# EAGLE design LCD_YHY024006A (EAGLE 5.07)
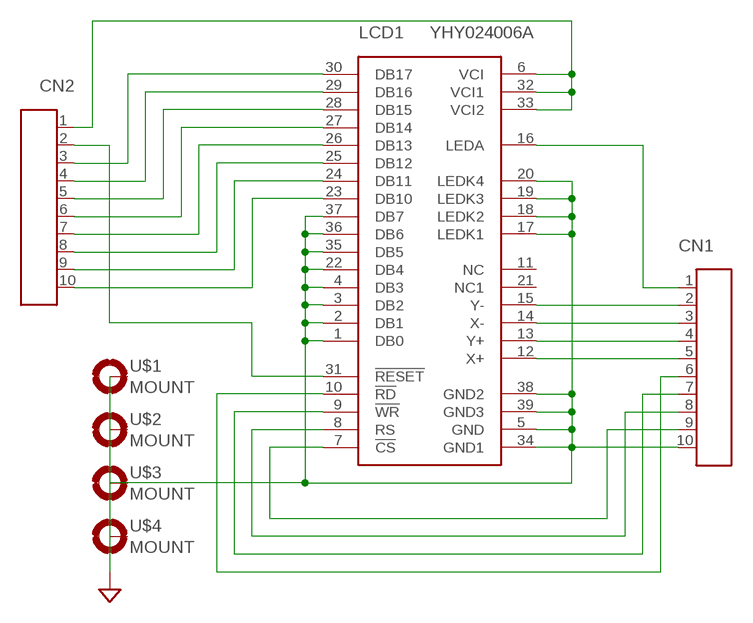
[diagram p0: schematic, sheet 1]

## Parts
CN1  CON_10P  [CON_HRS_DIP_10]
CN2  CON_10P  [CON_HRS_DIP_10]
LCD1  YHY024006A  LCD_YHY024006A  [LCD_YHY024006A]
U$1  MOUNT  MOUNT-PAD2.1  [PAD-2.1]
U$2  MOUNT  MOUNT-PAD2.1  [PAD-2.1]
U$3  MOUNT  MOUNT-PAD2.1  [PAD-2.1]
U$4  MOUNT  MOUNT-PAD2.1  [PAD-2.1]

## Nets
GND: CN1.10 LCD1.1(DB0) LCD1.2(DB1) LCD1.3(DB2) LCD1.4(DB3) LCD1.5(GND) LCD1.17(LEDK1) LCD1.18(LEDK2) LCD1.19(LEDK3) LCD1.20(LEDK4) LCD1.22(DB4) LCD1.34(GND1) LCD1.35(DB5) LCD1.36(DB6) LCD1.37(DB7) LCD1.38(GND2) LCD1.39(GND3) U$1.B2,1(MOUNT) U$2.B2,1(MOUNT) U$3.B2,1(MOUNT) U$4.B2,1(MOUNT)
N$1: CN2.3 LCD1.30(DB17)
N$2: CN2.4 LCD1.29(DB16)
N$3: CN2.5 LCD1.28(DB15)
N$4: CN2.6 LCD1.27(DB14)
N$5: CN2.7 LCD1.26(DB13)
N$6: CN2.8 LCD1.25(DB12)
N$7: CN2.9 LCD1.24(DB11)
N$8: CN2.10 LCD1.23(DB10)
N$9: CN2.2 LCD1.31(!RESET)
N$10: CN1.6 LCD1.10(!RD)
N$11: CN1.7 LCD1.9(!WR)
N$12: CN1.8 LCD1.8(RS)
N$13: CN1.9 LCD1.7(!CS)
N$14: CN1.2 LCD1.15(Y-)
N$15: CN1.3 LCD1.14(X-)
N$16: CN1.4 LCD1.13(Y+)
N$17: CN1.5 LCD1.12(X+)
N$19: CN2.1 LCD1.6(VCI) LCD1.32(VCI1) LCD1.33(VCI2)
N$20: CN1.1 LCD1.16(LEDA)
Unconnected: LCD1.11(NC) LCD1.21(NC1)

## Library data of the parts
CN1 CN2 = MyLib:CON_10P: 10P Molex Connector
LCD1 = MyLib:LCD_YHY024006A: 2.4" TFT Color LCD with Touch Screen
U$1-U$4 = MyLib:MOUNT-PAD: 2.1mm Mount Pad (Connectable to GND)

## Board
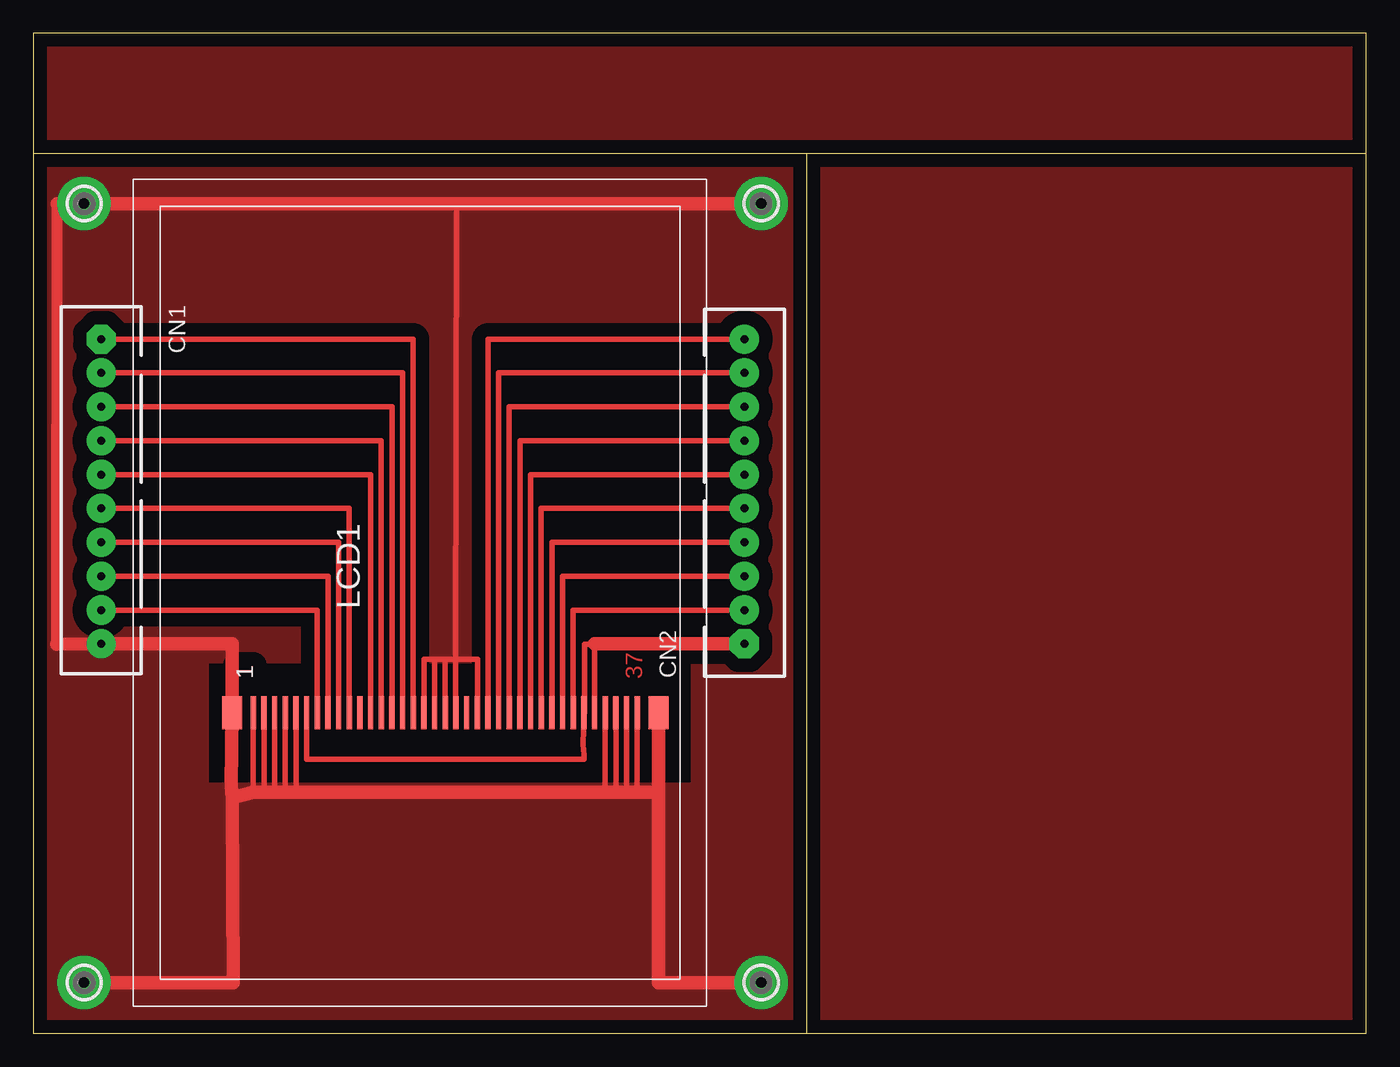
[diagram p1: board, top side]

Size 100 x 75 mm. Coordinates in mm from the lower left corner, seen from the top.
Outline: 58,0 0,0 0,66
Outline: 58,0 100,0 100,66
Outline: 100,66 100,75 0,75 0,66
Outline: 0,66 58,66
Outline: 58,66 100,66
Outline: 58,66 58,0
Copper layers (1*16): Top 0.035mm / dielectric 1.5mm / Bottom 0.035mm
Design rules "default": minimum track width 10mil, minimum drill 24mil, track to track 8mil, track to pad 8mil, pad to pad 8mil, via to via 8mil, smd to smd 8mil, copper to edge 40mil, drill to drill 8mil, minimum pad ring 10mil, minimum via ring 8mil, stop-mask expansion 4mil, vias tented up to drill 0mil, thermal gap 10mil

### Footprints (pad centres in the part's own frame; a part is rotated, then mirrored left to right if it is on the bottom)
CON_HRS_DIP_10 = drill 0.6 pad 2.184 octagon: 1 -11.43,0 | drill 0.6 pad 2.184 round: 2 -8.89,0; 3 -6.35,0; 4 -3.81,0; 5 -1.27,0; 6 1.27,0; 7 3.81,0; 8 6.35,0; 9 8.89,0; 10 11.43,0
LCD_YHY024006A = smd 2.5 x 0.4: 1 5,0; 2 5,-0.8; 3 5,-1.6; 4 5,-2.4; 5 5,-3.2; 6 5,-4; 7 5,-4.8; 8 5,-5.6; 9 5,-6.4; 10 5,-7.2; 11 5,-8; 12 5,-8.8; 13 5,-9.6; 14 5,-10.4; 15 5,-11.2; 16 5,-12; 17 5,-12.8; 18 5,-13.6; 19 5,-14.4; 20 5,-15.2; 21 5,-16; 22 5,-16.8; 23 5,-17.6; 24 5,-18.4; 25 5,-19.2; 26 5,-20; 27 5,-20.8; 28 5,-21.6; 29 5,-22.4; 30 5,-23.2; 31 5,-24; 32 5,-24.8; 33 5,-25.6; 34 5,-26.4; 35 5,-27.2; 36 5,-28; 37 5,-28.8 | smd 2.5 x 1.5: 38 5,1.6; 39 5,-30.4
PAD-2.1 = drill 0.8 pad 4 round: B2,1 0,0

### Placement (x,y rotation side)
CN1  5.08,40.64 270 top
CN2  53.34,40.64 90 top
LCD1  16.51,19.05 90 top
U$1  3.81,3.81 0 top
U$2  54.61,3.81 0 top
U$3  3.81,62.23 0 top
U$4  54.61,62.23 0 top

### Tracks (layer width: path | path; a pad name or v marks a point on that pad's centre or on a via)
GND
  Top 0.406: LCD1.1 16.5,19.05 16.5,18.09 | LCD1.2 17.3,19.05 17.3,18.09 | LCD1.3 18.1,19.05 18.1,18.09 | LCD1.4 18.9,19.05 18.9,18.09 | 19.7,19.05 LCD1.5 | 19.7,19.05 19.7,19.1 | 19.7,18.09 19.7,19.05 | LCD1.37 45.3,19.05 45.3,18.09 | LCD1.36 44.5,19.05 44.5,18.09 | LCD1.35 43.7,19.05 43.7,18.09 | LCD1.34 42.9,19.05 42.9,18.09 | 33.3,18.09 33.33,17.93 | 31.7,18.09 31.83,17.98 | 30.9,18.09 30.88,17.98 | 30.1,18.09 30.07,18.03 | 29.3,18.09 29.3,18.06 | 31.75,62.23 31.7,28.07 | LCD1.17 29.34,24.05 29.34,28.07 30.12,28.07 | 31.7,28.07 30.91,28.07 | 30.91,28.07 30.12,28.07 | LCD1.20 31.73,24.05 | LCD1.18 30.12,24.05 30.12,28.07 | LCD1.19 30.91,28.07 | LCD1.22 33.33,24.05 33.33,28.07 31.7,28.07 | LCD1.20 | 31.7,28.07 LCD1.20
  Top 0.813: 1.75,29.18 1.78,62.23
  Top 1.016: 14.94,17.68 14.83,18.59 LCD1.38 14.91,29.21 CN1.10 1.75,29.18 | 14.94,17.68 16.5,18.09 17.3,18.09 18.1,18.09 18.9,18.09 19.7,18.09 29.3,18.09 30.1,18.09 30.9,18.09 31.7,18.09 33.3,18.09 42.9,18.09 43.7,18.09 44.5,18.09 45.3,18.09 46.91,18.09 | 46.91,18.09 LCD1.39 | U$1.B2,1 14.99,3.81 14.94,17.68 | U$2.B2,1 46.91,3.81 46.91,18.09 | U$4.B2,1 31.75,62.23 U$3.B2,1 1.78,62.23
  pour Top (isolate 1.016, no thermals): 0,66.04 58.42,66.04 58.42,27.94 0,27.94
  pour Top (isolate 1.016, no thermals): 0,28.96 12.95,29.21 12.95,18.59 49.53,18.59 49.53,29.21 58.42,29.21 58.42,0 0,-0.25
N$1
  Top 0.406: LCD1.30 39.71,34.29 CN2.3
N$2
  Top 0.406: LCD1.29 38.91,36.83 CN2.4
N$3
  Top 0.406: LCD1.28 38.11,39.37 CN2.5
N$4
  Top 0.406: LCD1.27 37.31,41.91 CN2.6
N$5
  Top 0.406: LCD1.26 36.51,44.45 CN2.7
N$6
  Top 0.406: LCD1.25 35.71,46.99 CN2.8
N$7
  Top 0.406: LCD1.24 34.91,49.53 CN2.9
N$8
  Top 0.406: LCD1.23 34.11,52.07 CN2.10
N$9
  Top 0.406: LCD1.31 40.51,31.75 CN2.2
N$10
  Top 0.406: CN1.6 23.71,39.37 LCD1.10
N$11
  Top 0.406: CN1.7 22.91,36.83 LCD1.9
N$12
  Top 0.406: CN1.8 22.11,34.29 LCD1.8
N$13
  Top 0.406: CN1.9 21.31,31.75 LCD1.7
N$14
  Top 0.406: CN1.2 27.71,49.53 LCD1.15
N$15
  Top 0.406: CN1.3 26.91,46.99 LCD1.14
N$16
  Top 0.406: CN1.4 26.11,44.45 LCD1.13
N$17
  Top 0.406: CN1.5 25.31,41.91 LCD1.12
N$18
  pour Top (isolate 1.016, no thermals): 0,74.93 100.33,74.93 100.33,66.04 0,66.04
N$19
  Top 0.406: 42.09,29.18 42.09,28.88 42.11,28.88 LCD1.33 | 42.09,29.18 41.35,29.18 41.35,24.05 LCD1.32 41.26,21.64 41.3,20.9 41.3,20.55 20.5,20.55 20.5,24.05 LCD1.6 | 42.09,29.18 42.09,29.21
  Top 1.016: 42.09,29.21 CN2.1
N$20
  Top 0.406: CN1.1 28.51,52.07 LCD1.16
N$22
  pour Top (isolate 1.016, no thermals): 100.33,0 58.42,0 58.42,66.04 100.33,66.04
